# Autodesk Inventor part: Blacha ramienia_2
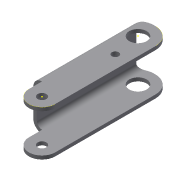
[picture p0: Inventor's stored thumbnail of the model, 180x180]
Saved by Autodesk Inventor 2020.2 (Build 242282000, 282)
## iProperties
Created: 2005-10
Part Number: Blacha ramienia_2
Document SubType Name: Modeling
Designer: F.Stasiak
Stock Number: Blacha ramienia_2
Material: Ogólny
Density: 1 g/cm^3
Appearance: Domyślna
Manager: www.cadconsulting.pl
Company: Fabian Stasiak CAD Consulting
Author: F.Stasiak
Subject: Zbiór ćwiczeń. Autodesk Inventor 2020. Kurs podstawowy
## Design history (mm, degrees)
sketch "Szkic1"
  geometry: L1 (-395.199, -54.254)-(-195.199, -54.254); L2 (-195.199, -54.254)-(-195.199, -654.254); L3 (-195.199, -654.254)-(-395.199, -654.254); L4 (-395.199, -654.254)-(-395.199, -54.254)
  constraints: 8 end point, 2 parallel, 1 horizontal, 1 perpendicular
  dimensions: "d0" = 600 distance of L3.end L1.start; "d1" = 200 distance of L2.end L3.end
extrude "Wyciągnięcie proste1" new body sketch "Szkic1" distance "d2" = 260; taper "d3" = 0 deg
fillet "Zaokrąglenie1" dims "d5" = 50, "d6" = 100
feature "Skorupa2" dims "d7" = 20
sketch "Szkic2"
  geometry: L1 (0, 240)-(150, 240) reference; L2 (150, 260)-(0, 260) reference; L3 (150, 240)-(150, 260) reference; L4 (150, 20)-(0, 20) reference; L5 (150, 0)-(0, 0) reference; L6 (150, 0)-(150, 20) reference; L7 (0, 0)-(0, 20); L8 (0, 240)-(0, 260)
  constraints: 4 end point, 2 equal length
extrude "Wyciągnięcie proste2" join sketch "Szkic2" distance "d8" = 150; taper "d9" = 0 deg
fillet "Zaokrąglenie2" dims "d10" = 75
sketch "Szkic3"
  geometry: A1 r 100 centre (-295.199, -154.254) between (-195.199, -154.254) and (-295.199, -54.254) reference; A2 r 75 centre (-270.199, -729.254) between (-345.199, -729.254) and (-195.199, -729.254) reference
hole "Otwór1" sketch "Szkic3" diameter "d11" = 100; stored, may be unused: countersink angle "d15" = 90 deg, drill point angle "d17" = 118 deg; dims "d12" = 6, "d13" = 4, "d14" = 2, "d16" = 8
hole "Otwór2" sketch "Szkic3" diameter "d18" = 50; stored, may be unused: countersink angle "d22" = 90 deg, drill point angle "d24" = 118 deg; dims "d19" = 6, "d20" = 4, "d21" = 2, "d23" = 8
chamfer "Faza1" distance "d25" = 50; stored, may be unused: second distance "d26" = 2, angle "d27" = 45 deg
fillet "Zaokrąglenie3" dims "d28" = 100
sketch "Szkic5"
  geometry: L1 (-270.199, -729.254)-(-270.199, -309.254); C1 r 25 at (-270.199, -729.254) reference; C2 r 20 at (-270.199, -309.254)
  constraints: 2 end point, 1 centre point, 1 coincident, 1 vertical
  dimensions: "d33" = 420 distance of L1.start L1.end; "d34" = 40 diameter of C2
extrude "Wyciągnięcie proste4" cut sketch "Szkic5" stored distance "d35" = 10; taper "d36" = 0 deg
node "Bryła1"
node "Korpusy bryłowe"
node "Korpusy powierzchniowe"
